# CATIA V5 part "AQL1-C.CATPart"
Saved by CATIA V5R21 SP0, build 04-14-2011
Part number: AQL1-C.SLDPRT
Bounding box of the stored display mesh (mm): x -0.689 to 0.811, y 0.802 to 2.702, z -1.283 to -0.493
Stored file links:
  C:\Users\user\Desktop\CATIA文件\0-最新文件\AQL1-C\AQL1-C.CATPart
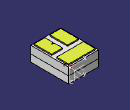
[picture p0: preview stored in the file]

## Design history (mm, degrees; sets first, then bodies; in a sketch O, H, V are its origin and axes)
AxisSystem1: origin (0.0609, 2.0131, -1.2826), X (-1, 0, 0), Y (0, 1, 0), Z (0, 0, -1)
Set1
  DatumSurface1 to DatumSurface14
  Line1: stored without definition
  Circle1: stored without definition
  Line2: stored without definition
  Circle2: stored without definition
  Line3: stored without definition
  Circle3: stored without definition
  Line4: stored without definition
  Circle4: stored without definition
  Line5: stored without definition
  Circle5: stored without definition
  Line6: stored without definition
  Circle6: stored without definition
  Line7: stored without definition
  Circle7: stored without definition
  Line8: stored without definition
  Circle8: stored without definition
  Line9 to Line20: stored without definition
  Circle9 to Circle16: stored without definition
  DatumSurface15 to DatumSurface20
  Line21 to Line32: stored without definition
  DatumSurface21 to DatumSurface26
  Line33 to Line44: stored without definition
  DatumSurface27 to DatumSurface35
  Line45 to Line65: stored without definition
  DatumSurface36 to DatumSurface43
  Line66 to Line83: stored without definition
  DatumSurface44 to DatumSurface51
  Line84 to Line101: stored without definition
  DatumSurface52 to DatumSurface57
  Line102 to Line113: stored without definition
  DatumSurface58 to DatumSurface67
  Line114 to Line137: stored without definition
  Point1 "几何中心": type Between, FirstPoint vertex [face of DatumSurface59], SecondPoint vertex [face of DatumSurface58], Ratio 0.5
  Point2 "发光中心（测试原点）": type Between, FirstPoint vertex [face of DatumSurface67], SecondPoint vertex [face of DatumSurface54], Ratio 0.5
  Point3: (0.0153, 0.0079, -0.0501), relative to Point2, in AxisSystem1
Body1 (main body)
